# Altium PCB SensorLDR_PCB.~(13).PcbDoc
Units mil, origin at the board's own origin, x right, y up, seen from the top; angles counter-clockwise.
Board outline 6000 x 4000 mil, 2 copper layers (Top Layer, Bottom Layer); 19 components, 11 nets, 54 pads, 0 vias.
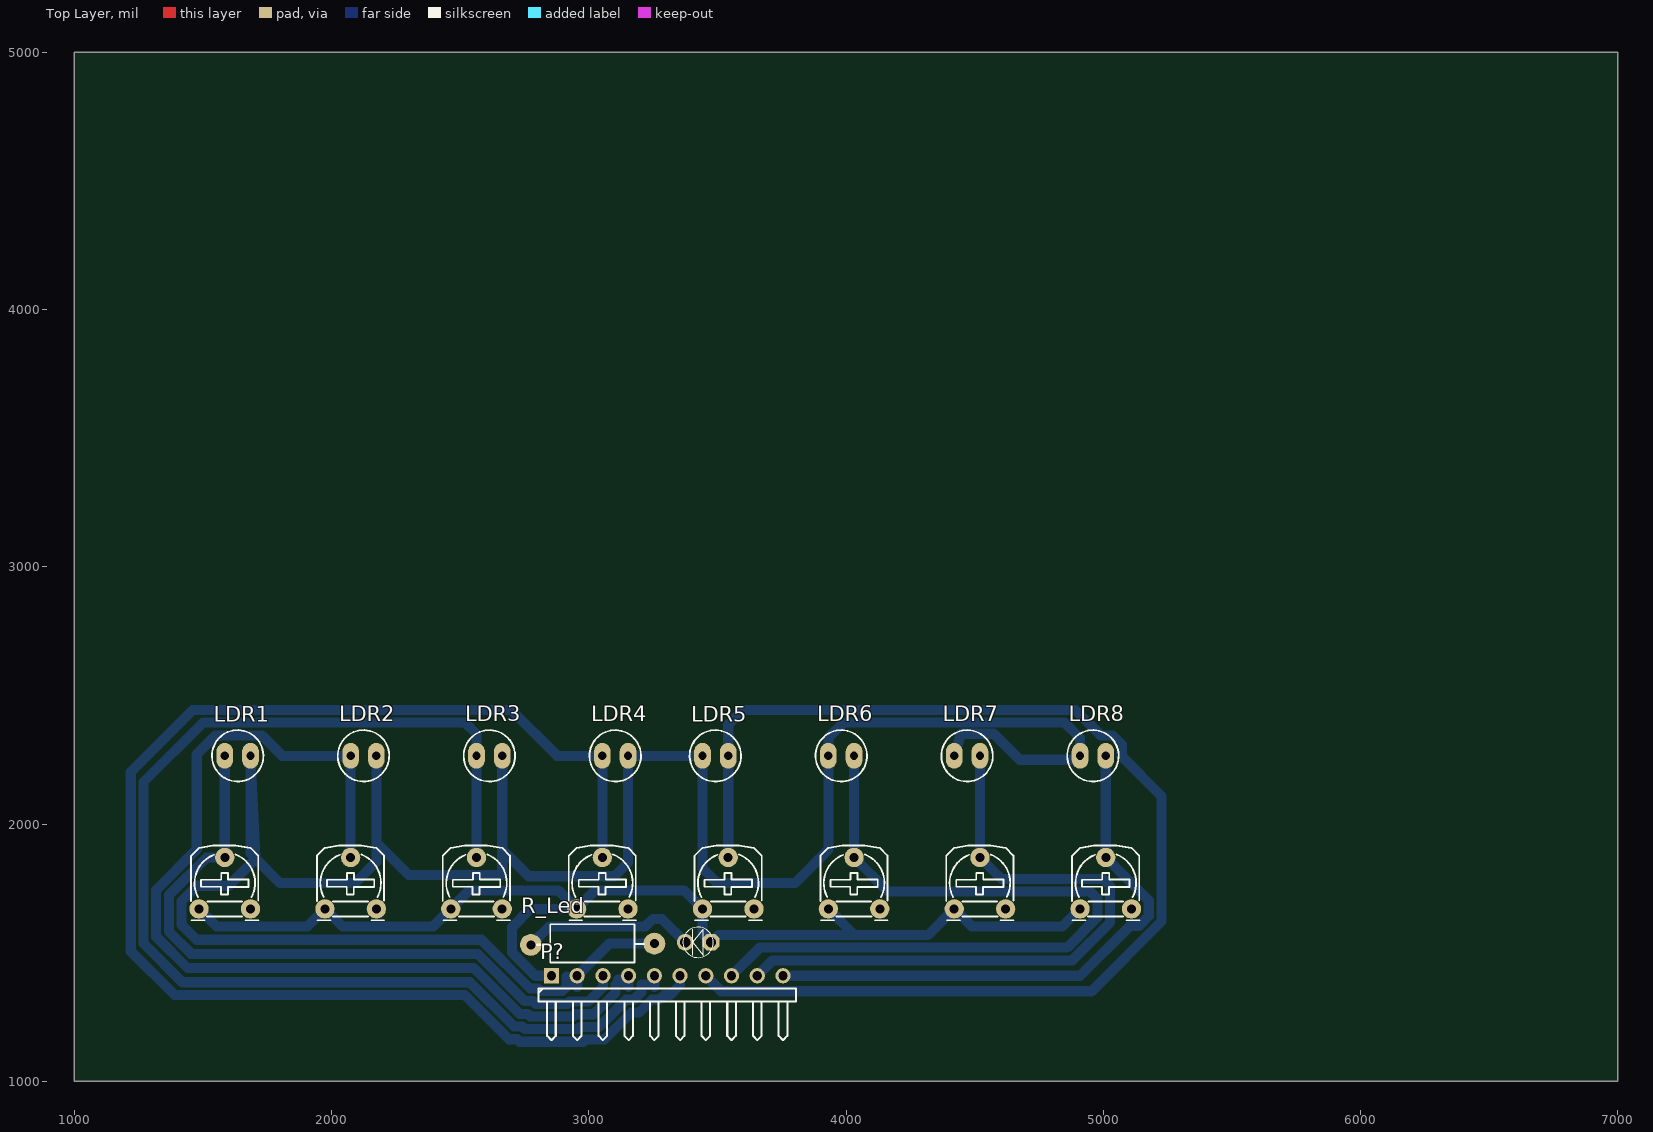
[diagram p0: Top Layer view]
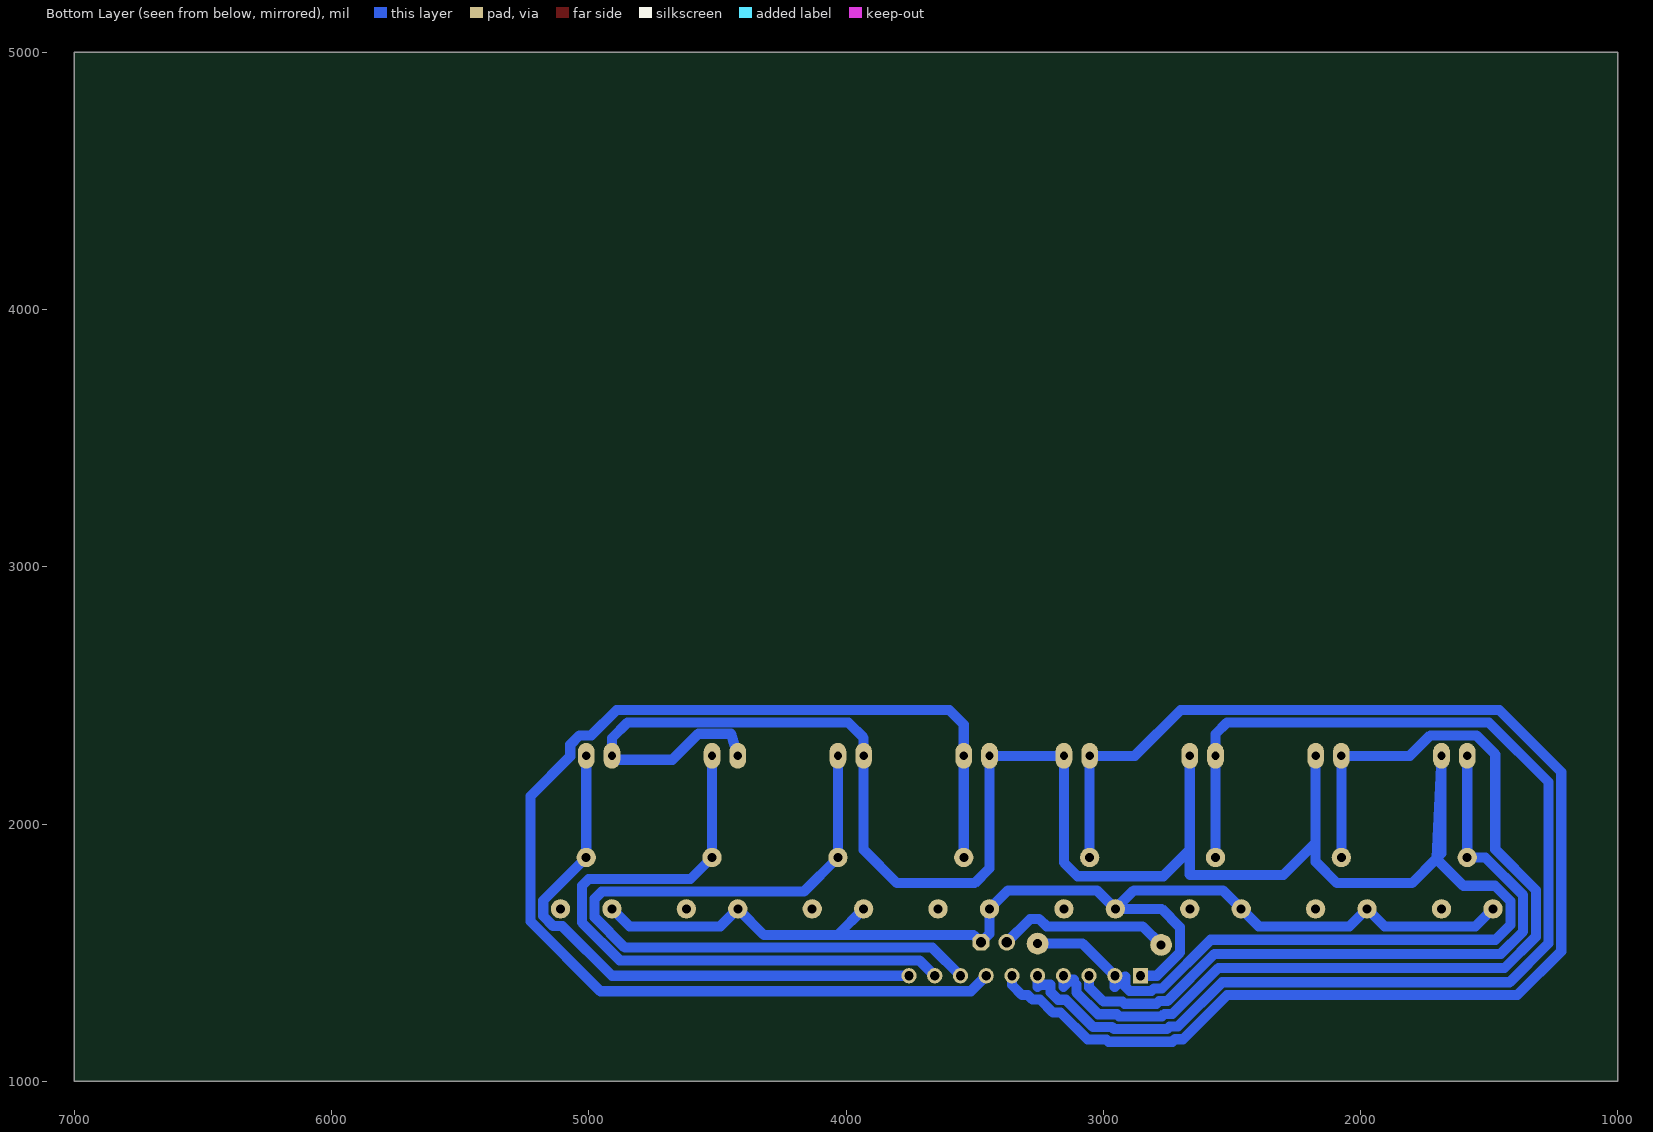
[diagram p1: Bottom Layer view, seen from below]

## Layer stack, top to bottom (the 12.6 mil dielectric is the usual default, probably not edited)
Top Solder: solder mask 0.4, Solder Resist, Dk 3.5
Top Layer: signal copper 1.4
Dielectric 1: dielectric 12.6, FR-4, Dk 4.8
Bottom Layer: signal copper 1.4
Bottom Solder: solder mask 0.4, Solder Resist, Dk 3.5

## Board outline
1000,1000 7000,1000 7000,5000 1000,5000

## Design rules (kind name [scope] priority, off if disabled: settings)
Clearance [All] p1: gap=10 ignorepadtopadclearanceinfootprint=FALSE except(0: Arc-Hole Track-Hole SMDPad-Hole THPad-Hole Via-Hole Fill-Hole Poly-Hole Region-Hole Text-Hole)
PolygonConnect [All] p1: connectstyle=Relief reliefconductorwidth=10 reliefentries=4 polygonreliefangle="90 Angle" airgapwidth=10
RoutingLayers [All] p1: top layer_v5=FALSE bottom layer_v5=TRUE
RoutingVias [All] p1: holewidth=28 width=50 viastyle="Through Hole" minholewidth=28 minwidth=50 maxholewidth=28 maxwidth=50
SolderMaskExpansion [All] p1: expansion=4
Width Others [All] p1: maxlimit=39.37 minlimit=39.37 preferedwidth=39.37
Width VCC [InNet('VCC')] p2: maxlimit=39.37 minlimit=39.37 preferedwidth=39.37
Width GND [InNet('GND')] p3: maxlimit=39.37 minlimit=39.37 preferedwidth=39.37
29 further rules are at their usual default settings.

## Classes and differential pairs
component class SensorLDR: LDR1 LDR2 LDR3 LDR4 LDR5 LDR6 LDR7 LDR8 P? R_Led

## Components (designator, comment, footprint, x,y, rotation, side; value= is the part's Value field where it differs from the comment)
LDR1 "LDR" CDS 1685,2265 r180 top
LDR2 "LDR" CDS 2174.29,2265 r180 top
LDR3 "LDR" CDS 2663.57,2265 r180 top
LDR4 "LDR" CDS 3152.86,2265 r180 top
LDR5 "LDR" CDS 3442.14,2265 r0 top
LDR6 "LDR" CDS 3931.43,2265 r0 top
LDR7 "LDR" CDS 4420.71,2265 r0 top
LDR8 "LDR" CDS 4910,2265 r0 top
LED? "LED" LED-3MM-YELLOW 3475,1540 r180 top value="LED 3 ly Single Colour"
P? "Header 10H" HDR1X10H 2855,1410 r0 top
R_Led "Res" RES-1/2W 2995,1535 r0 top
VR1 "50K" VR-S2 1485,1670 r0 top value="Volume 50k"
VR2 "50K" VR-S2 1974.29,1670 r0 top value="Volume 50k"
VR3 "50K" VR-S2 2463.57,1670 r0 top value="Volume 50k"
VR4 "50K" VR-S2 2952.86,1670 r0 top value="Volume 50k"
VR5 "50K" VR-S2 3442.14,1670 r0 top value="Volume 50k"
VR6 "50K" VR-S2 3931.43,1670 r0 top value="Volume 50k"
VR7 "50K" VR-S2 4420.71,1670 r0 top value="Volume 50k"
VR8 "50K" VR-S2 4910,1670 r0 top value="Volume 50k"

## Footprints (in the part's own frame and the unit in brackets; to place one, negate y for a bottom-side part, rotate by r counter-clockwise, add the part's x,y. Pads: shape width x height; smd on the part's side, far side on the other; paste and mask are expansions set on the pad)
CDS [mil] "QUANG TRO"
  oval 65x100 hole 32: 1(0,0) 2(100,0)
  silkscreen extent -50,-100 150,100, body extent -53,-80 153,89, height 138
HDR1X10H [mm] "Connector; Header; 10 Position; Right Angle"
  rect 1.5x1.5 hole 0.9: 1(0,0)
  round 1.5 hole 0.9: 2(2.54,0) 3(5.08,0) 4(7.62,0) 5(10.16,0) 6(12.7,0) 7(15.24,0) 8(17.78,0) 9(20.32,0) 10(22.86,0)
  silkscreen extent -1.27,-6.35 24.13,-1.27
LED-3MM-YELLOW [mil]
  oct 65x65 hole 40: 1(0,0)
  round 65 hole 40: 2(100,0)
  silkscreen extent -9,-59 109,59, body extent -27,-77 117,80, height 181
RES-1/2W [mil]
  round 85 hole 35: 1(-220,-5) 2(260,0)
  silkscreen extent -195,-74 221,75, body extent -230,-60 270,56, height 121
VR-S2 [mil] "Resistor Variable"
  round 75 hole 35: 1(0,0) 2(100,200) 3(200,0)
  silkscreen extent -31,-44 231,246, body extent -87,-30 307,372, height 165

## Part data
LDR1 LDR2 LDR3 LDR4 LDR5 LDR6 LDR7 LDR8: "Quang Tro"
LED?: "LED Single colour Green and Red"
P?: "Header, 10-Pin, Right Angle"
R_Led: Manufacturer="Generic Components"
VR1 VR2 VR3 VR4 VR5 VR6 VR7 VR8: library part VR-S, "Var Resistor"

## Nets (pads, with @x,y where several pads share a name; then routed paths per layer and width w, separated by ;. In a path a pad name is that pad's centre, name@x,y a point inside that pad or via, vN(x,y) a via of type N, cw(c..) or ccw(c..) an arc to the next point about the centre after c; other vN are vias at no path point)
GND: LDR1.1 LDR2.1 LDR3.1 LDR4.1 LDR5.1 LDR6.1 LDR7.1 LDR8.1 P?.2 R_Led.2 | length 9714.3
  Bottom Layer w39.37: LDR2.1 2174.29,1927.71 ; LDR3.1 2663.57,1900 ; R_Led.2 3080,1535 P?.2 2955,1367 2914.21,1407.79 2914.21,1368.18 2896.82,1350.79 2813.18,1350.79 2803.33,1360.63 2771.55,1360.63 2582.18,1550 1475,1550 1417,1608 1417,1700 1477,1760 1600,1760 1705,1865 ; LDR7.1 4446.71,2351 4574,2351 4675,2250 4895,2250 LDR8.1 4910,2334 4850,2394 3990.43,2394 3931.43,2335 LDR6.1 3931.43,1900 3801.43,1770 3500,1770 3442.14,1827.86 LDR5.1 LDR4.1 3152.86,1849.86 3100,1797 2766.57,1797 2663.57,1900 ; 1705,1865 1800,1770 2091,1770 2174.29,1853.29 2174.29,1927.71 ; 1705,1865 1685,1885 LDR1.1 1705,1865 ; 2174.29,1927.71 2300,1802 2662.57,1802 2663.57,1803 2663.57,1900
NetLED?_2: LED?.2 R_Led.1 | length 679.5
  Bottom Layer w39.37: R_Led.1 2847,1602 3220,1602 3249,1631 3284,1631 LED?.2
S1: LDR1.2 P?.3 VR1.2 | length 2688.8
  Bottom Layer w39.37: LDR1.2 VR1.2 1514.53,1870 1367.63,1723.1 1367.63,1582.19 1454.82,1495 2567.36,1495 2751.1,1311.26 2782.88,1311.26 2792.73,1301.42 2917.27,1301.42 2925.86,1310 2999.39,1310 3055,1365.61 P?.3
S2: LDR2.2 P?.4 VR2.2 | length 3934.9
  Bottom Layer w39.37: VR2.2 LDR2.2 1808,2265 1728.31,2344.69 1550,2344.69 1476,2270.69 1476,1901.29 1318.26,1743.55 1318.26,1561.74 1440,1440 2552.54,1440 2730.65,1261.89 2762.43,1261.89 2772.28,1252.05 2937.72,1252.05 2946.31,1260.63 3019.84,1260.63 3104.37,1345.16 3104.37,1375.63 3114.21,1385.47 3114.21,1395 3126,1395 3155,1366 P?.4
S3: LDR3.2 P?.5 VR3.2 | length 4774.8
  Bottom Layer w39.37: VR3.2 LDR3.2 2563.57,2350 2519.52,2394.06 1500,2394.06 1268.89,2162.95 1268.89,1536.11 1420,1385 2537.72,1385 2710.2,1212.52 2741.98,1212.52 2751.83,1202.68 2958.17,1202.68 2966.76,1211.26 3040.29,1211.26 3145.66,1316.63 3175.45,1316.63 3204.37,1345.55 3204.37,1375 3246.89,1375 3255,1366.89 P?.5
S4: LDR4.2 P?.6 VR4.2 | length 5508
  Bottom Layer w39.37: VR4.2 LDR4.2 2877,2265 2698.57,2443.43 1460.43,2443.43 1219.52,2202.52 1219.52,1505.48 1390,1335 2517.9,1335 2689.75,1163.15 2721.54,1163.15 2731.38,1153.31 2978.62,1153.31 2987.21,1161.89 3060.74,1161.89 3166.11,1267.26 3195.9,1267.26 3246.16,1317.52 3275.45,1317.52 3292.93,1335 3316.24,1335 3355,1373.76 P?.6
S5: LDR5.2 P?.7 VR5.2 | length 4785.9
  Bottom Layer w39.37: P?.7 3515,1350 4955,1350 5226.56,1621.56 5226.56,2108.44 5072.19,2262.81 5072.19,2308.26 5035.76,2344.69 4990.31,2344.69 4891.57,2443.43 3598.57,2443.43 3542.14,2387 LDR5.2 VR5.2
S6: LDR6.2 P?.8 VR6.2 | length 2996.2
  Bottom Layer w39.37: P?.8 3664.37,1519.37 3694.55,1519.37 4859.55,1519.37 4977.19,1637.01 4977.19,1710 4950,1737.19 4164.24,1737.19 VR6.2 LDR6.2
S7: LDR7.2 P?.9 VR7.2 | length 2547
  Bottom Layer w39.37: P?.9 3715,1470 4880,1470 5026.56,1616.56 5026.56,1760 5000,1786.56 4604.16,1786.56 VR7.2 LDR7.2
S8: LDR8.2 P?.10 VR8.2 | length 2210.4
  Bottom Layer w39.37: P?.10 4910,1410 5102.81,1602.81 5137.83,1602.81 5177.19,1642.17 5177.19,1677.19 5177.19,1702.81 VR8.2 LDR8.2
VCC: LED?.1 P?.1 VR1.1 VR2.1 VR3.1 VR4.1 VR5.1 VR6.1 VR7.1 VR8.1 | length 4590.6
  Bottom Layer w39.37: VR1.1 1553,1602 1906.29,1602 VR2.1 2042.29,1602 2395.57,1602 VR3.1 2535.57,1742 2880.86,1742 VR4.1 ; P?.1 2792,1410 2702,1500 2702,1599 2773,1670 VR4.1 ; VR6.1 4032.69,1568.74 ; VR8.1 4842,1602 4488.71,1602 VR7.1 4319.45,1568.74 4032.69,1568.74 ; VR4.1 3024.86,1742 3370.14,1742 VR5.1 3442.14,1572.86 LED?.1 3503.74,1568.74 4032.69,1568.74
pads on no net: VR1.3 VR2.3 VR3.3 VR4.3 VR5.3 VR6.3 VR7.3 VR8.3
